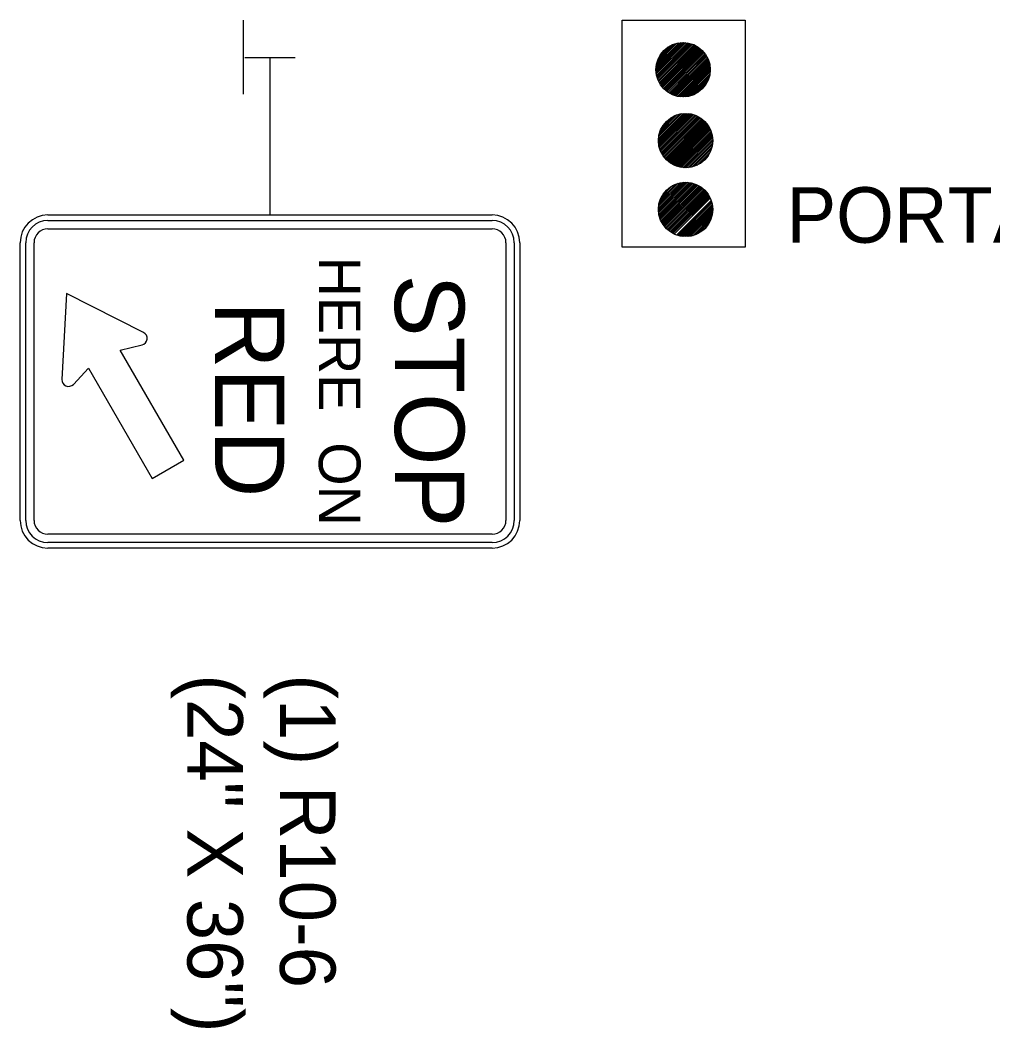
# Model space of a CAD drawing. Extents: x 1926586 to 1930787, y 596452 to 599566.
# Drawn here: x 1928187.4 to 1928292.6, y 599284.6 to 599393.5 of the extents above; entities that cross this region are included whole.
import ezdxf

# ---------------------------------------------------------------- set-up
doc = ezdxf.new("R2010")
doc.units = 0
for name, color, linetype in [('Default', 7, 'Continuous'), ('P_TC_Signs_Permanent', 7, 'Continuous'), ('R_Border', 7, 'Continuous')]:
    doc.layers.add(name, color=color, linetype=linetype)

msp = doc.modelspace()

# ---------------------------------------------------------------- linework, layer by layer
at = {"layer": 'Default'}
for p, q in [((1928211.59, 599385.5), (1928211.59, 599393.5)), ((1928256.14, 599388.01), (1928259.21, 599391.09)), ((1928256.14, 599388.19), (1928259.03, 599391.09)), ((1928256.14, 599388.38), (1928258.84, 599391.08)), ((1928256.15, 599387.85), (1928259.38, 599391.08)), ((1928256.17, 599388.59), (1928258.64, 599391.06)), ((1928256.17, 599387.69), (1928259.54, 599391.05)), ((1928256.2, 599387.53), (1928259.69, 599391.03)), ((1928256.21, 599388.81), (1928258.42, 599391.02)), ((1928256.24, 599387.39), (1928259.84, 599390.99)), ((1928256.28, 599387.25), (1928259.98, 599390.95)), ((1928256.28, 599389.06), (1928258.17, 599390.95)), ((1928256.32, 599387.11), (1928260.11, 599390.9)), ((1928256.38, 599386.98), (1928260.24, 599390.85)), ((1928256.39, 599389.35), (1928257.87, 599390.83)), ((1928256.43, 599386.86), (1928260.37, 599390.79)), ((1928256.49, 599386.74), (1928260.49, 599390.73)), ((1928256.56, 599386.63), (1928260.6, 599390.67)), ((1928256.61, 599389.75), (1928257.48, 599390.62)), ((1928256.63, 599386.52), (1928260.71, 599390.6)), ((1928256.71, 599386.41), (1928260.82, 599390.52)), ((1928256.78, 599386.31), (1928260.92, 599390.44)), ((1928256.87, 599386.21), (1928261.02, 599390.36)), ((1928256.95, 599386.11), (1928261.11, 599390.27)), ((1928211.71, 599389.48), (1928217.17, 599389.48)), ((1928257.04, 599386.02), (1928261.2, 599390.18)), ((1928257.14, 599385.94), (1928261.29, 599390.09)), ((1928257.24, 599385.85), (1928261.37, 599389.99)), ((1928257.34, 599385.78), (1928261.45, 599389.89)), ((1928257.44, 599385.7), (1928261.52, 599389.78)), ((1928257.56, 599385.63), (1928261.59, 599389.67)), ((1928257.67, 599385.57), (1928261.66, 599389.56)), ((1928257.79, 599385.5), (1928261.72, 599389.44)), ((1928257.91, 599385.45), (1928261.78, 599389.31)), ((1928258.04, 599385.4), (1928261.83, 599389.18)), ((1928258.18, 599385.35), (1928261.88, 599389.05)), ((1928258.32, 599385.31), (1928261.92, 599388.91)), ((1928258.46, 599385.27), (1928261.95, 599388.76)), ((1928258.61, 599385.24), (1928261.98, 599388.61)), ((1928258.77, 599385.22), (1928262, 599388.45)), ((1928258.94, 599385.21), (1928262.02, 599388.28)), ((1928259.12, 599385.21), (1928262.02, 599388.11)), ((1928259.31, 599385.22), (1928262.01, 599387.92)), ((1928259.52, 599385.24), (1928261.99, 599387.71)), ((1928259.74, 599385.28), (1928261.94, 599387.49)), ((1928259.99, 599385.35), (1928261.87, 599387.24)), ((1928260.28, 599385.47), (1928261.76, 599386.94)), ((1928260.68, 599385.68), (1928261.54, 599386.54)), ((1928256.41, 599380.35), (1928259.48, 599383.43)), ((1928256.41, 599380.53), (1928259.3, 599383.43)), ((1928256.41, 599380.72), (1928259.11, 599383.42)), ((1928256.42, 599380.19), (1928259.65, 599383.42)), ((1928256.44, 599380.93), (1928258.91, 599383.4)), ((1928256.44, 599380.03), (1928259.81, 599383.39)), ((1928256.47, 599379.87), (1928259.96, 599383.37)), ((1928256.48, 599381.15), (1928258.69, 599383.36)), ((1928256.51, 599379.73), (1928260.11, 599383.33)), ((1928256.55, 599379.59), (1928260.25, 599383.29)), ((1928256.55, 599381.4), (1928258.44, 599383.29)), ((1928256.59, 599379.45), (1928260.38, 599383.24)), ((1928256.65, 599379.33), (1928260.51, 599383.19)), ((1928256.66, 599381.69), (1928258.14, 599383.17)), ((1928256.7, 599379.2), (1928260.64, 599383.13)), ((1928256.76, 599379.08), (1928260.75, 599383.07)), ((1928256.83, 599378.97), (1928260.87, 599383.01)), ((1928256.88, 599382.09), (1928257.74, 599382.96)), ((1928256.9, 599378.86), (1928260.98, 599382.94)), ((1928256.97, 599378.75), (1928261.09, 599382.86)), ((1928257.05, 599378.65), (1928261.19, 599382.78)), ((1928257.14, 599378.55), (1928261.29, 599382.7)), ((1928257.22, 599378.46), (1928261.38, 599382.61)), ((1928257.31, 599378.36), (1928261.47, 599382.52)), ((1928257.41, 599378.28), (1928261.56, 599382.43)), ((1928257.51, 599378.2), (1928261.64, 599382.33)), ((1928257.61, 599378.12), (1928261.72, 599382.23)), ((1928257.71, 599378.04), (1928261.79, 599382.12)), ((1928257.82, 599377.97), (1928261.86, 599382.01)), ((1928257.94, 599377.91), (1928261.93, 599381.9)), ((1928258.06, 599377.85), (1928261.99, 599381.78)), ((1928258.18, 599377.79), (1928262.05, 599381.65)), ((1928258.31, 599377.74), (1928262.1, 599381.52)), ((1928258.45, 599377.69), (1928262.15, 599381.39)), ((1928258.59, 599377.65), (1928262.19, 599381.25)), ((1928258.73, 599377.61), (1928262.22, 599381.1)), ((1928258.88, 599377.58), (1928262.25, 599380.95)), ((1928259.04, 599377.56), (1928262.27, 599380.79)), ((1928259.21, 599377.55), (1928262.29, 599380.62)), ((1928259.39, 599377.55), (1928262.29, 599380.45)), ((1928259.58, 599377.56), (1928262.28, 599380.26)), ((1928259.78, 599377.58), (1928262.26, 599380.05)), ((1928260.01, 599377.62), (1928262.21, 599379.83)), ((1928260.26, 599377.69), (1928262.14, 599379.58)), ((1928260.55, 599377.81), (1928262.03, 599379.28)), ((1928260.95, 599378.03), (1928261.81, 599378.88)), ((1928256.41, 599372.84), (1928259.56, 599375.99)), ((1928256.41, 599373.01), (1928259.38, 599375.99)), ((1928256.41, 599373.2), (1928259.2, 599375.99)), ((1928256.43, 599372.68), (1928259.72, 599375.97)), ((1928256.43, 599373.39), (1928259, 599375.97)), ((1928256.45, 599372.52), (1928259.88, 599375.94)), ((1928256.46, 599373.61), (1928258.79, 599375.94)), ((1928256.48, 599372.37), (1928260.03, 599375.91)), ((1928256.51, 599373.85), (1928258.55, 599375.88)), ((1928256.52, 599372.23), (1928260.17, 599375.87)), ((1928256.57, 599372.09), (1928260.31, 599375.83)), ((1928256.61, 599374.12), (1928258.28, 599375.79)), ((1928256.62, 599371.96), (1928260.44, 599375.78)), ((1928256.67, 599371.83), (1928260.57, 599375.73)), ((1928256.73, 599371.71), (1928260.69, 599375.67)), ((1928256.76, 599374.46), (1928257.94, 599375.64)), ((1928256.79, 599371.59), (1928260.81, 599375.61)), ((1928256.86, 599371.48), (1928260.92, 599375.54)), ((1928256.93, 599371.37), (1928261.03, 599375.47)), ((1928257.01, 599371.27), (1928261.13, 599375.39)), ((1928257.09, 599371.16), (1928261.23, 599375.31)), ((1928257.17, 599371.07), (1928261.33, 599375.22)), ((1928257.26, 599370.98), (1928261.42, 599375.14)), ((1928257.35, 599370.89), (1928261.51, 599375.04)), ((1928257.45, 599370.8), (1928261.6, 599374.95)), ((1928257.55, 599370.72), (1928261.68, 599374.85)), ((1928257.65, 599370.64), (1928261.75, 599374.74)), ((1928257.76, 599370.57), (1928261.83, 599374.63)), ((1928257.88, 599370.5), (1928261.89, 599374.52)), ((1928257.99, 599370.44), (1928261.96, 599374.41)), ((1928258.11, 599370.38), (1928262.02, 599374.28)), ((1928258.37, 599370.28), (1928262.12, 599374.03)), ((1928258.51, 599370.23), (1928262.17, 599373.89)), ((1928258.65, 599370.19), (1928262.2, 599373.75)), ((1928258.8, 599370.16), (1928262.24, 599373.6)), ((1928258.95, 599370.14), (1928262.26, 599373.44)), ((1928259.12, 599370.12), (1928262.28, 599373.28)), ((1928259.29, 599370.11), (1928262.29, 599373.11)), ((1928259.47, 599370.11), (1928262.29, 599372.92)), ((1928259.67, 599370.13), (1928262.27, 599372.73)), ((1928259.88, 599370.16), (1928262.24, 599372.52)), ((1928260.12, 599370.21), (1928262.19, 599372.28)), ((1928260.38, 599370.3), (1928262.1, 599372.02)), ((1928260.71, 599370.44), (1928261.95, 599371.69)), ((1928261.28, 599370.84), (1928261.56, 599371.11))]:
    msp.add_line(p, q, dxfattribs=at)
msp.add_lwpolyline([(1928252.5, 599393.5), (1928265.79, 599393.5), (1928265.79, 599368.97), (1928252.5, 599368.97)], close=True, dxfattribs=at)
for centre in [(1928259.08, 599388.15), (1928259.35, 599380.49), (1928259.35, 599373.05)]:
    msp.add_circle(centre, 2.94, dxfattribs=at)
at = {"layer": 'P_TC_Signs_Permanent'}
for p, q in [((1928190.44, 599372.45), (1928238.44, 599372.45)), ((1928190.44, 599371.85), (1928238.44, 599371.85)), ((1928190.44, 599370.95), (1928238.44, 599370.95)), ((1928187.44, 599339.45), (1928187.44, 599369.45)), ((1928188.04, 599339.45), (1928188.04, 599369.45)), ((1928188.94, 599339.45), (1928188.94, 599369.45)), ((1928239.94, 599369.45), (1928239.94, 599339.45)), ((1928240.84, 599369.45), (1928240.84, 599339.45)), ((1928241.44, 599369.45), (1928241.44, 599339.45)), ((1928238.44, 599337.95), (1928190.44, 599337.95)), ((1928238.44, 599337.05), (1928190.44, 599337.05)), ((1928238.44, 599336.45), (1928190.44, 599336.45))]:
    msp.add_line(p, q, dxfattribs=at)
for points in [[(1928200.78, 599359.75), (1928192.46, 599363.95), (1928191.95, 599354.68)], [(1928193.19, 599354.15), (1928194.84, 599355.89), (1928201.72, 599343.97), (1928205.13, 599345.94), (1928198.25, 599357.86), (1928200.62, 599358.41)]]:
    msp.add_lwpolyline(points, dxfattribs=at)
for centre, radius, start, end in [((1928190.44, 599369.45), 3, 90, 180), ((1928190.44, 599369.45), 2.4, 90, 180), ((1928238.44, 599369.45), 3, 360, 90), ((1928238.44, 599369.45), 2.4, 360, 90), ((1928190.44, 599369.45), 1.5, 90, 180), ((1928238.44, 599369.45), 1.5, 360, 90), ((1928200.45, 599359.11), 0.72, 283.0349, 63.2286), ((1928192.67, 599354.64), 0.72, 176.857, 316.6377), ((1928190.44, 599339.45), 3, 180, 270), ((1928190.44, 599339.45), 2.4, 180, 270), ((1928190.44, 599339.45), 1.5, 180, 270), ((1928238.44, 599339.45), 3, 270, 360), ((1928238.44, 599339.45), 2.4, 270, 360), ((1928238.44, 599339.45), 1.5, 270, 360)]:
    msp.add_arc(centre, radius, start, end, dxfattribs=at)
at = {"layer": 'R_Border'}
msp.add_line((1928214.44, 599389.48), (1928214.44, 599372.45), dxfattribs=at)

# ---------------------------------------------------------------- texts
at = {"layer": 'Default'}
msp.add_text('PORTABLE TRAFFIC SIGNAL SYSTEM', height=5.9996, rotation=360, dxfattribs=at).set_placement((1928270.27, 599369.45))
at = {"layer": 'P_TC_Signs_Permanent'}
for s, height, p in [('HERE  ON', 4.5, (1928219.72, 599367.95)), ('STOP', 7.5, (1928227.94, 599366.01)), ('RED', 7.5, (1928208.5, 599363.12))]:
    msp.add_text(s, height=height, rotation=270, dxfattribs=at).set_placement(p)
at = {"layer": 'R_Border'}
for s, height, p in [('(24" X 36")', 5.9996, (1928205.51, 599322.81)), ('(1) R10-6', 6, (1928215.52, 599322.81))]:
    msp.add_text(s, height=height, rotation=270, dxfattribs=at).set_placement(p)

doc.saveas('drawing.dxf')
